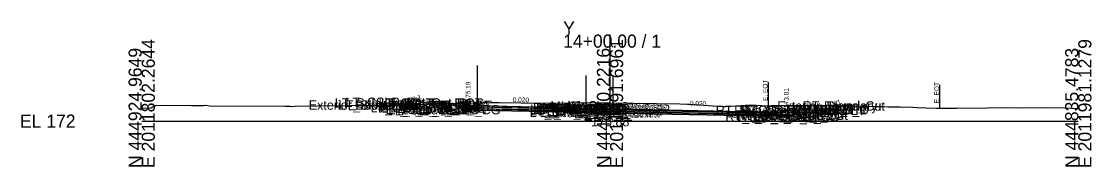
# Model space of a CAD drawing. Extents: x -26 to 3203, y -10 to 9532.
# Drawn here: x -25.7 to 202.8, y 7990.3 to 8021.2 of the extents above; entities that cross this region are included whole.
import ezdxf

# ---------------------------------------------------------------- set-up
doc = ezdxf.new("R2010")
doc.units = 0
for name, color, linetype in [('Default', 7, 'Continuous'), ('Exist Cross Section Cell', 7, 'Continuous'), ('Exist XS Center Line Elevation Label', 7, 'Continuous'), ('Exist XS Ground Line', 7, 'Continuous'), ('Prop CMT Conc Surface', 7, 'Continuous'), ('Prop CMT Concrete Structures', 7, 'Continuous'), ('Prop CMT Pvmt Course 1', 7, 'Continuous'), ('Prop CMT Pvmt Course 1 CG', 7, 'Continuous'), ('Prop CMT Pvmt Course 2', 7, 'Continuous'), ('Prop CMT Pvmt Course 3', 7, 'Continuous'), ('Prop CMT Pvmt Surface', 7, 'Continuous'), ('Prop CMT Slope Grass', 7, 'Continuous'), ('Prop CMT Subgrade Earthwork', 7, 'Continuous'), ('Prop Plan Preparation Sketches Hydraulic Ditch', 7, 'Continuous'), ('Prop XS Hydro Elevations', 7, 'Continuous'), ('Prop XS Label Text', 7, 'Continuous'), ('Prop XS SE Text', 7, 'Continuous'), ('Prop XS Side Slope Text', 7, 'Continuous'), ('Scratch_Level_0', 7, 'Continuous')]:
    doc.layers.add(name, color=color, linetype=linetype)

msp = doc.modelspace()

# ---------------------------------------------------------------- linework, layer by layer
at = {"layer": 'Exist Cross Section Cell'}
for p, q in [((100, 8000), (100, 8018.45)), ((0, 8000), (100, 8000)), ((100, 8000), (200, 8000))]:
    msp.add_line(p, q, dxfattribs=at)
at = {"layer": 'Exist XS Ground Line'}
msp.add_lwpolyline([(0, 8002.78), (2.03, 8002.82), (2.38, 8003.06), (3.01, 8003.36), (4.32, 8003.37), (10.64, 8003.36), (13.21, 8003.33), (13.71, 8003.37), (14.5, 8003.28), (30.57, 8003.16), (31.64, 8003.17), (32.05, 8003.14), (32.6, 8003.17), (37.52, 8003.23), (50.98, 8003.4), (60.34, 8003.63), (61.84, 8003.67), (74.45, 8003.94), (76.36, 8003.95), (80.97, 8003.89), (83.81, 8003.85), (85.24, 8003.81), (91.27, 8003.89), (96.42, 8003.98), (98.58, 8003.9), (100, 8003.88), (114.88, 8003.67), (116.53, 8003.64), (117.02, 8003.61), (123.95, 8003.08), (124.84, 8003.13), (130.02, 8003.47), (132.51, 8003.35), (133.74, 8003.29), (134.39, 8003.3), (136.73, 8003.31), (137.65, 8003.31), (139.51, 8003.34), (141.37, 8003.33), (142.3, 8003.32), (145.11, 8003.32), (146.43, 8003.3), (147.9, 8003.28), (150.68, 8003.23), (153.46, 8003.19), (156.42, 8003.11), (158.51, 8003.09), (159.44, 8003.07), (161.96, 8003.01), (164.64, 8002.95), (165.56, 8002.92), (167.49, 8002.86), (169.63, 8002.79), (170.37, 8002.76), (174, 8002.73), (180.54, 8002.85), (183.83, 8002.87), (188.17, 8002.85), (192.73, 8002.87), (197.07, 8002.82), (200, 8002.72)], dxfattribs=at)
at = {"layer": 'Prop CMT Conc Surface'}
for points in [[(69.68, 8003.19), (69.68, 8003.69), (69.18, 8003.69)], [(71.68, 8003.23), (69.68, 8003.19)], [(135.64, 8001.93), (137.64, 8001.81)], [(137.64, 8001.81), (137.64, 8002.31), (138.14, 8002.31)]]:
    msp.add_lwpolyline(points, dxfattribs=at)
at = {"layer": 'Prop CMT Concrete Structures'}
for p, q in [((97.68, 8003.22), (95.67, 8003.18)), ((99.94, 8003.06), (97.68, 8003.22)), ((94.92, 8002.93), (94.91, 8002.76)), ((95.67, 8003.18), (94.92, 8002.93)), ((100.69, 8002.81), (99.94, 8003.06)), ((100.7, 8002.64), (100.69, 8002.81))]:
    msp.add_line(p, q, dxfattribs=at)
for points in [[(71.68, 8003.23), (69.68, 8003.19), (69.68, 8003.69), (69.18, 8003.69)], [(69.18, 8003.69), (69.18, 8002.7), (71.68, 8002.65)], [(71.68, 8002.65), (71.68, 8003.23)], [(94.91, 8002.76), (100.7, 8002.64)], [(135.64, 8001.93), (137.64, 8001.81), (137.64, 8002.31), (138.14, 8002.31)], [(138.14, 8002.31), (138.14, 8001.3), (135.64, 8001.35)], [(135.64, 8001.35), (135.64, 8001.93)]]:
    msp.add_lwpolyline(points, dxfattribs=at)
at = {"layer": 'Prop CMT Pvmt Course 1'}
for points in [[(71.68, 8003.23), (71.68, 8002.98)], [(93.67, 8002.78), (76.96, 8003.12)], [(76.96, 8002.87), (93.67, 8002.53)], [(93.67, 8002.78), (101.95, 8002.62)], [(93.67, 8002.53), (93.67, 8002.78)], [(93.67, 8002.53), (93.67, 8002.78)], [(101.95, 8002.37), (93.67, 8002.53)], [(101.95, 8002.62), (101.95, 8002.37)], [(101.95, 8002.62), (135.64, 8001.93)], [(101.95, 8002.37), (101.95, 8002.62)], [(135.64, 8001.68), (101.95, 8002.37)], [(135.64, 8001.93), (135.64, 8001.68)]]:
    msp.add_lwpolyline(points, dxfattribs=at)
for points in [[(93.67, 8002.53), (93.67, 8002.66), (93.67, 8002.66), (93.67, 8002.53)], [(101.95, 8002.37), (101.95, 8002.49), (101.95, 8002.49), (101.95, 8002.37)]]:
    msp.add_lwpolyline(points, close=True, dxfattribs=at)
at = {"layer": 'Prop CMT Pvmt Course 1 CG'}
for points in [[(71.68, 8002.65), (68.68, 8002.71), (68.35, 8002.38)], [(68.35, 8002.38), (71.68, 8002.32)], [(71.68, 8002.32), (71.68, 8002.65)], [(135.64, 8001.35), (138.64, 8001.29), (138.98, 8000.95)], [(135.64, 8001.02), (135.64, 8001.35)], [(138.98, 8000.95), (135.64, 8001.02)]]:
    msp.add_lwpolyline(points, dxfattribs=at)
at = {"layer": 'Prop CMT Pvmt Course 2'}
for points in [[(93.67, 8002.53), (71.68, 8002.98)], [(71.68, 8002.98), (71.68, 8002.65)], [(76.96, 8002.54), (93.67, 8002.2)], [(93.67, 8002.53), (101.95, 8002.37)], [(93.67, 8002.2), (93.67, 8002.53)], [(93.67, 8002.2), (93.67, 8002.53)], [(101.95, 8002.03), (93.67, 8002.2)], [(101.95, 8002.37), (101.95, 8002.03)], [(101.95, 8002.03), (101.95, 8002.37)], [(101.95, 8002.37), (135.64, 8001.68)], [(135.64, 8001.35), (101.95, 8002.03)], [(135.64, 8001.68), (135.64, 8001.35)]]:
    msp.add_lwpolyline(points, dxfattribs=at)
at = {"layer": 'Prop CMT Pvmt Course 3'}
for points in [[(93.67, 8002.2), (71.68, 8002.65)], [(71.68, 8002.65), (71.68, 8002.32)], [(71.68, 8002.32), (93.67, 8001.87)], [(93.67, 8002.2), (101.95, 8002.03)], [(93.67, 8001.87), (93.67, 8002.2)], [(93.67, 8001.87), (93.67, 8002.2)], [(101.95, 8001.7), (93.67, 8001.87)], [(101.95, 8002.03), (101.95, 8001.7)], [(101.95, 8002.03), (135.64, 8001.35)], [(101.95, 8001.7), (101.95, 8002.03)], [(135.64, 8001.02), (101.95, 8001.7)], [(135.64, 8001.35), (135.64, 8001.02)]]:
    msp.add_lwpolyline(points, dxfattribs=at)
at = {"layer": 'Prop CMT Pvmt Surface'}
for points in [[(93.67, 8002.78), (71.68, 8003.23)], [(93.67, 8002.78), (101.95, 8002.62)], [(101.95, 8002.62), (135.64, 8001.93)]]:
    msp.add_lwpolyline(points, dxfattribs=at)
at = {"layer": 'Prop CMT Slope Grass'}
for points in [[(69.18, 8003.69), (59.68, 8003.88), (58.82, 8003.6)], [(147.14, 8002.49), (147.64, 8002.5), (149.87, 8003.24)], [(138.14, 8002.31), (147.14, 8002.49)]]:
    msp.add_lwpolyline(points, dxfattribs=at)
at = {"layer": 'Prop CMT Subgrade Earthwork'}
for points in [[(71.68, 8002.32), (68.35, 8002.38), (67, 8003.74)], [(93.67, 8001.87), (71.68, 8002.32)], [(93.67, 8001.87), (101.95, 8001.7)], [(101.95, 8001.7), (135.64, 8001.02)], [(135.64, 8001.02), (138.98, 8000.95), (140.39, 8002.36)]]:
    msp.add_lwpolyline(points, dxfattribs=at)
at = {"layer": 'Prop Plan Preparation Sketches Hydraulic Ditch'}
for p, q in [((71.68, 8003.23), (71.68, 8011.87)), ((94.91, 8002.76), (94.91, 8009.7)), ((100.7, 8002.64), (100.7, 8009.7))]:
    msp.add_line(p, q, dxfattribs=at)
at = {"layer": 'Prop XS Label Text'}
for p, q in [((133.74, 8008.29), (133.74, 8003.29)), ((170.37, 8007.76), (170.37, 8002.76))]:
    msp.add_line(p, q, dxfattribs=at)

# ---------------------------------------------------------------- texts
at = {"layer": 'Default'}
msp.add_text('-', height=0.0001, dxfattribs=at).set_placement((0, 8000))
at = {"layer": 'Exist Cross Section Cell'}
for s, p in [('Y', (90, 8018.45)), ('14+00.00 / 1', (90, 8015.65)), ('EL 172', (-26, 7998.6))]:
    msp.add_text(s, height=2.8, dxfattribs=at).set_placement(p)
for s, p in [('E 2011802.2644', (2.8, 7990)), ('E 2011891.6961', (102.8, 7990)), ('E 2011981.1279', (202.8, 7990)), ('N 444924.9649', (0, 7990)), ('N 444880.2216', (100, 7990)), ('N 444835.4783', (200, 7990))]:
    msp.add_text(s, height=2.8, rotation=90, dxfattribs=at).set_placement(p)
at = {"layer": 'Exist XS Center Line Elevation Label'}
msp.add_text('175.88', height=2, dxfattribs=at).set_placement((95.96, 7998.88))
msp.add_text('175.88', height=2, dxfattribs=at).set_placement((95.96, 7998.88))
at = {"layer": 'Prop XS Hydro Elevations'}
for s, p in [('175.19', (70.18, 8004.19)), ('173.81', (138.14, 8002.81))]:
    msp.add_text(s, height=1, rotation=90, dxfattribs=at).set_placement(p)
at = {"layer": 'Prop XS Label Text'}
for p in [(133.64, 8004.31), (170.27, 8003.78)]:
    msp.add_text('E. EOT', height=1, rotation=90, dxfattribs=at).set_placement(p)
at = {"layer": 'Prop XS SE Text'}
for p in [(79.23, 8004.08), (117.06, 8003.31)]:
    msp.add_text('0.020', height=1, rotation=358.8357, dxfattribs=at).set_placement(p)
at = {"layer": 'Prop XS Side Slope Text'}
for rotation, p in [(18.4349, (58.01, 8004.12)), (16.6022, (147.56, 8003.14))]:
    msp.add_text('3:1', height=1, rotation=rotation, dxfattribs=at).set_placement(p)
at = {"layer": 'Scratch_Level_0'}
for s, p in [('Exterior Boundary', (35.67, 8002.42)), ('LT_Sub_Trench_Out_DLT', (41.2, 8002.87)), ('LT_Slope_Fill', (42.05, 8002.42)), ('LT_CSLP_Pnt', (43.49, 8003.01)), ('LT_CG1_Shelf_Out', (48.86, 8001.84)), ('LT_CG_Top_Face', (50.57, 8002.82)), ('LT_CG_Top_BOC', (51.1, 8002.82)), ('LT_CG_Bot_BOC', (51.13, 8001.83)), ('LT_CG_Top_Gut', (51.55, 8002.32)), ('LT_Sub_OEOP', (52.1, 8001.51)), ('LT_Sub_OEOT_CG', (52.68, 8001.44)), ('LT_CG_Bot_IE', (55.23, 8001.78)), ('LT_Sub_OEOT', (55.39, 8001.44)), ('LT_PV2_OEOT', (55.49, 8002.11)), ('LT_PV3_OEOT', (55.49, 8001.78)), ('LT_PV1_OEOT', (56.05, 8002.36)), ('LT_PV2_OEEOP', (82.96, 8001.54)), ('LT_PV3_OEEOP', (82.96, 8001.2)), ('LT_PV1_OEEOP', (83.53, 8001.66)), ('LT_PV2_IEEOP', (83.61, 8001.54)), ('LT_PV1_IEEOP', (84.17, 8001.66)), ('LT_PV2_PGL1', (84.54, 8001.54)), ('LT_PV3_PGL1', (84.54, 8001.2)), ('LT_PV2_PGL', (84.87, 8001.54)), ('LT_PV1_PGL', (85.43, 8001.79)), ('MI_Face In', (85.55, 8001.95)), ('MI_Top In', (87.27, 8002.2)), ('MI_Crown', (90.85, 8002.27)), ('RT_PV2_OEEOP', (91.16, 8001.37)), ('RT_PV1_OEEOP', (91.72, 8001.49)), ('RT_PV2_IEEOP', (91.8, 8001.37)), ('MI_Face Out', (92.15, 8001.78)), ('MI_Top Out', (92.37, 8002.03)), ('RT_PV1_IEEOP', (92.37, 8001.49)), ('RT_PV2_PGL1', (92.73, 8001.37)), ('RT_PV2_PGL', (93.06, 8001.37)), ('MI_Bot Out', (93.16, 8001.62)), ('RT_PV1_PGL', (93.63, 8001.62)), ('RT_Sub_Trench_Out_DLT', (122.58, 8001.32)), ('RT_CG_Top_Face', (126.53, 8001.28)), ('RT_CG_Top_BOC', (128.05, 8001.28)), ('Exterior Boundary', (135.7, 8002.22)), ('RT_Slope_Cut', (141.15, 8002.22)), ('RT_Shld_O', (141.35, 8001.46)), ('CSLP_Pnt', (142.18, 8001.47)), ('LT_Sub_OEEOP', (82.87, 8000.87)), ('LT_PV4_PGL', (84.87, 8000.87)), ('RT_Sub_OEEOP', (91.06, 8000.7)), ('RT_PV3_OEEOP', (91.16, 8001.03)), ('RT_PV3_PGL1', (92.73, 8001.03)), ('RT_PV4_PGL', (93.06, 8000.7)), ('RT_Sub_OEOT_CG', (124.64, 7999.98)), ('RT_CG1_Shelf_Out', (126.82, 8000.25)), ('RT_CG_Bot_IE', (127.18, 8000.31)), ('RT_Sub_OEOT', (127.34, 7999.98)), ('RT_PV2_OEOT', (127.44, 8000.65)), ('RT_PV3_OEOT', (127.44, 8000.31)), ('RT_CG_Top_Gut', (127.5, 8000.78)), ('RT_PV1_OEOT', (128.01, 8000.9)), ('RT_CG_Bot_BOC', (128.08, 8000.26)), ('RT_Sub_OEOP', (130.72, 7999.91))]:
    msp.add_text(s, height=2, dxfattribs=at).set_placement(p)

doc.saveas('drawing.dxf')
